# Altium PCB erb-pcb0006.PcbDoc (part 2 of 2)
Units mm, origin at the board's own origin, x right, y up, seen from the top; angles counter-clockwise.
Board outline 100 x 66.5 mm, 4 copper layers (Top Layer, Mid-Layer 1, Mid-Layer 2, Bottom Layer), stack 1.564 mm thick; 134 components, 81 nets, 741 pads, 81 vias.
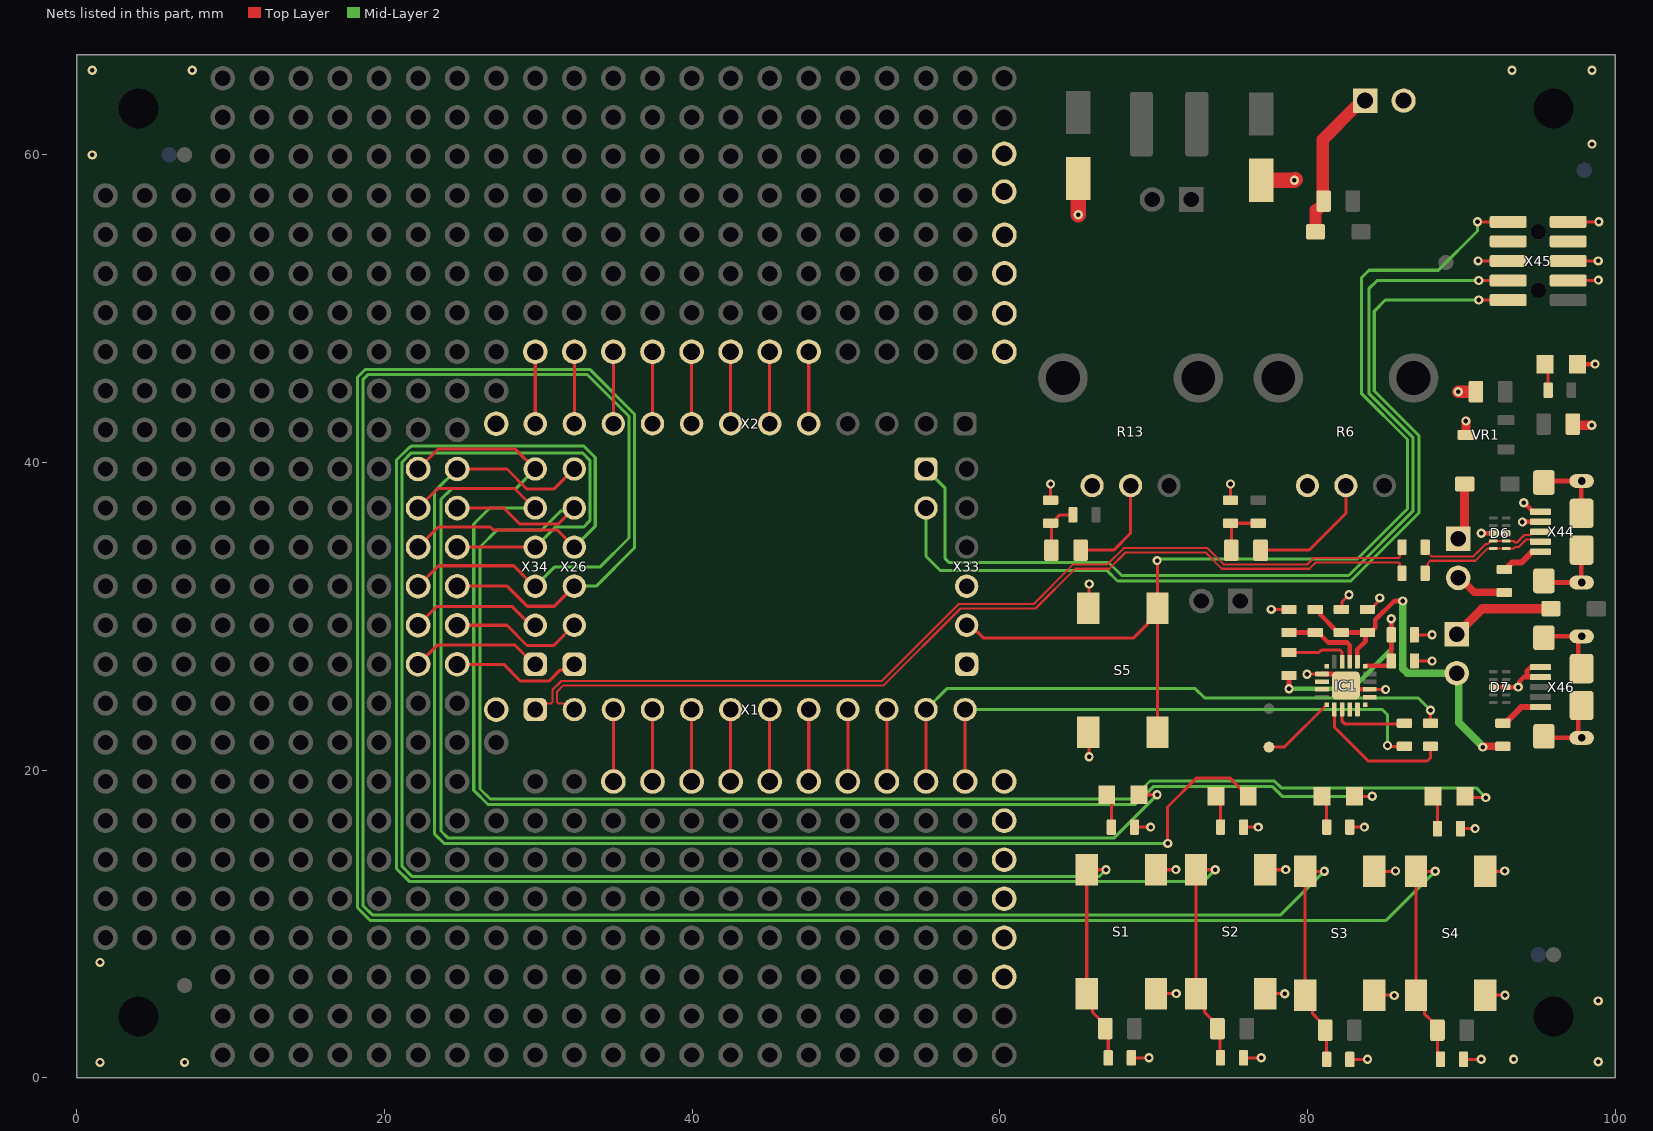
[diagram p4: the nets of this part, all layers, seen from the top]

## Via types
v1: diameter 0.6, hole 0.3, Top Layer to Bottom Layer, 81 vias

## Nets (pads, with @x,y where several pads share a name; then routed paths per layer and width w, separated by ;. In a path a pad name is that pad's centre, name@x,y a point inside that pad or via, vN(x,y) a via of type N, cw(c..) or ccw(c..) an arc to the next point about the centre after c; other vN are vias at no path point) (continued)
GND: C1.2 C2.2 C3.2 C4.2 C5.2 C6.2 C7.2 C8.2 C9.2 C10.2 C11.1 C12.1 C13.1 C14.1 D5.K D6.3 D6.8 D7.3 D7.8 IC1.3 IC1.12 IC1.21 R3.1 R4.1 R6.1 R7.1 R9.1 R13.1 R16.2 S1.3 S1.4 S2.3 S2.4 S3.3 S3.4 S4.3 S4.4 S5.3 S5.4 VR1.3 X33.1 X33.3 X44.4 X44.5 X44.6@95.375,32.3 X44.6@95.375,38.7 X44.6@97.825,32.2 X44.6@97.825,34.3 X44.6@97.825,36.7 X44.6@97.825,38.8 X45.3 X45.5 X45.9 X46.4 X46.5 X46.6@95.375,22.2 X46.6@95.375,28.6 X46.6@97.825,22.1 X46.6@97.825,24.2 X46.6@97.825,26.6 X46.6@97.825,28.7 X47.2 X52.1 X53.1 X54.1 X55.1 X56.1 X57.1 X58.1 X59.1 X60.1 X61.1 X62.1 X63.1 X64.1 X65.1 | length 76.1
  Top Layer w0.2: C7.2@63.3,37.55 v1(63.3,38.6) ; S5.4@65.8,22.1 65.8,20.874 v1(65.803,20.872) ; S5.3@65.8,30.9 65.8,32.092 v1(65.81,32.102) ; C1.2@68.55,1.3 v1(69.7,1.3) ; R3.1@68.95,16.3 v1(69.8,16.3) ; S1.3@70.15,5.475 71.471,5.475 v1(71.472,5.474) ; S1.4@70.15,13.525 71.435,13.525 v1(71.448,13.538) ; C3.2@75,37.55 v1(75,38.6) ; C2.2@75.85,1.3 v1(77,1.3) ; R4.1@76.05,16.3 v1(76.8,16.3) ; S2.3@77.25,5.475 78.509,5.475 v1(78.517,5.466) ; S2.4@77.25,13.525 78.576,13.525 v1(78.587,13.536) ; v1(77.65,30.45) R16.2@78.8,30.45 ; v1@80.021,26.238 80.025,26.243 IC1.12@80.943,26.243 ; C14.1@82.2,30.45 82.233,30.483 82.233,30.933 v1(82.7,31.4) ; C4.2@82.75,1.2 v1(83.9,1.2) ; R7.1@82.95,16.3 v1(83.7,16.3) ; C13.1@83.9,30.45 84.1,30.45 84.3,30.65 84.3,30.66 84.478,30.838 84.546,30.906 84.546,30.938 84.7,31.092 v1(84.7,31.2) ; IC1.3@84.16,25.24 v1(85.078,25.24) ; S3.3@84.35,5.375 85.615,5.375 v1(85.635,5.354) ; S3.4@84.35,13.425 85.704,13.425 v1(85.723,13.444) ; C11.1@86.95,27.1 v1(88.1,27.1) ; C12.1@86.95,28.8 v1(88.1,28.8) ; R9.1@89.95,16.2 v1(90.9,16.2) ; C8.2@90.15,1.2 v1(91.3,1.2) ; S4.3@91.55,5.375 92.828,5.375 v1(92.841,5.362) ; S4.4@91.55,13.425 92.807,13.425 v1(92.826,13.444) ; X45.3@96.95,51.835 98.89,51.835 v1(98.913,51.858) ; X45.5@96.95,53.105 v1(98.905,53.105) ; X45.9@96.95,55.645 v1(98.945,55.645)
  Top Layer w0.3: IC1.12@80.95,26.25 81.316,26.25 81.317,26.251 81.708,26.251 82.409,25.55 IC1.21@82.55,25.55 ; IC1.21@82.5,25.5 82.749,25.251 83.749,25.251 IC1.3@84.05,25.25 ; v1(91.3,35.4) D6.3@92.915,35.4 ; D7.3@92.07,25.4 D7.3@92.085,25.4 D7.8@92.915,25.4 v1(93.7,25.4) 93.757,25.457 93.757,25.745 94.071,26.059 94.441,26.059 ; v1(93.975,36.133) 93.992,36.15 X44.4@95.125,36.15 ; v1(94.056,37.385) 94.083,37.385 94.6,36.868 94.6,36.85 94.65,36.8 X44.5@95.125,36.8 ; 94.45,26.059 94.441,26.059 ; X46.6@95.15,22.2 95.25,22.1 97.6,22.1 X46.6@97.6,24.2 ; X46.4@95.15,26.05 94.45,26.05 94.441,26.059 ; X46.5@95.15,26.7 94.5,26.7 94.274,26.474 94.274,26.226 94.441,26.059 ; X46.6@95.15,28.6 95.25,28.7 97.6,28.7 X46.6@97.6,26.6 ; X44.6@95.35,32.3 95.45,32.2 97.8,32.2 X44.6@97.8,34.3 ; X44.6@95.35,38.7 95.45,38.8 97.8,38.8 X44.6@97.8,36.7 ; D5.K@97.55,46.4 v1(98.7,46.4)
  Top Layer w0.6: VR1.3@90.3,41.8 v1(90.3,42.7) ; C5.2@97.325,42.425 v1(98.475,42.425)
  Top Layer w0.8: v1(89.8,44.6) C6.2@90.63,44.6
  Top Layer w1: v1(65.1,56.1) C10.2@65.1,58.45 ; C9.2@77,58.35 v1(79.15,58.35) v1@79.2,58.4
  other v1: 1.5,1 7,1 98.91,1.05 93.4,1.2 98.9,5 1.5,7.5 79.971,26.238 1,60 98.5,60.7 1,65.5 7.5,65.5 93.3,65.5 98.5,65.5
GPIO1: D1.A X34.6 X40.1 | length 86.3
  Top Layer w0.2: X40.1@22.18,39.58 23.472,40.872 28.508,40.872 X34.6@29.8,39.58 ; D1.A@69.05,18.4 v1(70.225,18.4)
  Mid-Layer 2 w0.2: X34.6@29.8,39.58 28.52,38.3 24.365,38.3 23.67,37.605 23.67,16.047 24.137,15.58 67.405,15.58 v1(70.225,18.4)
GPIO2: D2.A X26.6 X32.1 | length 89.5
  Top Layer w0.2: X32.1@24.72,39.58 27.957,39.58 29.267,38.27 30.996,38.27 X26.6@32.323,39.597 ; v1(70.913,15.236) 70.9,15.249 70.9,17.6 72.8,19.5 74.946,19.5 75.646,18.8 75.876,18.8 D2.A@75.976,18.7
  Mid-Layer 2 w0.2: X32.1@24.72,39.58 23.235,38.095 23.235,15.87 23.875,15.23 70.907,15.23 v1(70.913,15.236)
GPIO3: D3.A X34.5 X39.1 | length 91.1
  Top Layer w0.2: X39.1@22.18,37.04 23.456,38.316 28.445,38.316 29.721,37.04 X34.5@29.8,37.04 ; D3.A@83.05,18.3 v1@84.2,18.3
  Mid-Layer 2 w0.2: X34.5@29.8,37.04 26.84,37.04 25.8,36 25.8,18.695 26.725,17.77 68.817,17.77 69.997,18.95 77.703,18.95 78.353,18.3 v1(84.205,18.3)
GPIO4: D4.A X26.5 X31.1 | length 99.1
  Top Layer w0.2: X31.1@24.72,37.04 27.752,37.04 28.792,36 31.3,36 X26.5@32.34,37.04 ; D4.A@90.25,18.3 90.304,18.304 90.469,18.304 90.587,18.187 90.619,18.219 v1(91.596,18.219)
  Mid-Layer 2 w0.2: X26.5@32.34,37.04 32.14,36.84 31.44,36.84 30.2,35.6 27.3,35.6 26.21,34.51 26.21,18.78 26.87,18.12 68.584,18.12 69.764,19.3 77.848,19.3 78.298,18.85 83.977,18.85 90.966,18.85 v1@91.416,18.399
GPIO5: C1.1 R1.1 S1.1 S1.2 X34.4 X38.1 | length 112.5
  Top Layer w0.2: X38.1@24.72,34.5 X34.4@29.8,34.5 ; v1(66.9,13.525) S1.2@65.65,13.525 S1.1@65.65,5.475 66.026,5.099 66.026,4.267 66.505,3.788 66.526,3.788 66.9,3.415 66.9,3.2 67.05,3.05 C1.1@67.05,1.3
  Mid-Layer 2 w0.2: X34.4@29.8,34.5 31.1,35.8 32.933,35.8 33.35,36.217 33.35,40.15 32.87,40.63 21.745,40.63 21.13,40.015 21.13,13.745 21.775,13.1 66.475,13.1 v1(66.9,13.525)
GPIO6: C2.1 R2.1 S2.1 S2.2 X26.4 X30.1 | length 125.6
  Top Layer w0.2: X30.1@22.18,34.5 23.483,35.803 26.883,35.803 27.076,35.611 31.229,35.611 X26.4@32.34,34.5 ; v1(74,13.525) S2.2@72.75,13.525 S2.1@72.75,5.475 73.311,4.914 73.311,4.267 R2.1@74.15,3.429 ; R2.1@74.15,3.2 74.318,3.032 74.318,1.332 C2.1@74.35,1.3
  Mid-Layer 2 w0.2: X26.4@32.34,34.5 33.7,35.86 33.7,40.325 32.955,41.07 21.745,41.07 21.655,40.98 21.6,40.98 20.78,40.16 20.78,13.6 21.63,12.75 73.225,12.75 v1(74,13.525)
GPIO7: C4.1 R8.1 S3.1 S3.2 X34.3 X37.1 | length 154.7
  Top Layer w0.2: X37.1@22.18,31.96 23.507,33.287 28.394,33.287 X34.3@29.721,31.96 ; v1(81.1,13.425) S3.2@79.85,13.425 S3.1@79.85,5.375 80.336,4.889 80.336,4.167 80.787,3.716 80.787,3.413 81.25,2.95 C4.1@81.25,1.2
  Mid-Layer 2 w0.2: X34.3@29.8,31.96 31.04,33.2 34,33.2 35.89,35.09 35.89,43.01 33.19,45.71 18.91,45.71 18.59,45.39 18.59,11.205 19.205,10.59 78.265,10.59 v1(81.1,13.425)
GPIO8: C8.1 R14.1 S4.1 S4.2 X26.3 X29.1 | length 162
  Top Layer w0.2: X29.1@24.72,31.96 27.978,31.96 29.281,30.657 31.037,30.657 X26.3@32.34,31.96 ; R14.1@88.076,3.688 87.597,4.167 87.597,4.828 S4.1@87.05,5.375 S4.2@87.05,13.425 v1(88.3,13.425) ; R14.1@88.076,3.688 88.45,3.315 C8.1@88.45,1.2
  Mid-Layer 2 w0.2: X26.3@32.34,31.96 33.76,31.96 36.24,34.44 36.24,43.155 33.335,46.06 19.06,46.06 18.765,46.06 18.24,45.535 18.24,45.24 18.24,11.06 19.06,10.24 85.115,10.24 v1(88.3,13.425)
GPIO9: X34.2 X36.1 | length 8.6
  Top Layer w0.2: X36.1@22.18,29.42 23.41,30.65 28.275,30.65 29.505,29.42 X34.2@29.8,29.42
GPIO10: X26.2 X28.1 | length 8.7
  Top Layer w0.2: X28.1@24.72,29.42 27.957,29.42 29.267,28.11 30.996,28.11 X26.2@32.323,29.437
GPIO11: X34.1 X35.1 | length 8.6
  Top Layer w0.2: X35.1@22.18,26.88 23.45,28.15 28.451,28.15 X34.1@29.721,26.88
GPIO12: X26.1 X27.1 | length 8.5
  Top Layer w0.2: X27.1@24.72,26.88 27.752,26.88 28.832,25.8 30.7,25.8 31.399,26.499 31.959,26.499 X26.1@32.34,26.88
GPIO13: X1.3 X21.1 | length 5.1
  Top Layer w0.2: X21.1@34.88,19.26 X1.3@34.88,24.34
GPIO14: X1.4 X19.1 | length 5.1
  Top Layer w0.2: X19.1@37.42,19.26 X1.4@37.42,24.34
GPIO15: X2.12 X4.1 | length 5.1
  Top Layer w0.2: X2.12@29.8,42.12 X4.1@29.8,47.2
I2C_SCL: X1.5 X17.1 | length 5.1
  Top Layer w0.2: X17.1@39.96,19.26 X1.5@39.96,24.34
I2C_SDA: X1.6 X15.1 | length 5.1
  Top Layer w0.2: X15.1@42.5,19.26 X1.6@42.5,24.34
NC_DBG_CON_2.7: X45.7
NC_DBG_CON_2.8: X45.8
NC_GPIO0_CP2102: IC1.2
NC_GPIO1_CP2102: IC1.1
NC_GPIO2_CP2102: IC1.20
NC_GPIO3_CP2102: IC1.19
NC_nSuspend_CP2102: IC1.11
NC_Suspend_CP2102: IC1.14
NC_Wakeup_CP2102: IC1.13
NetC3_1: C3.1 R5.1 R20.1 | length 3.6
  Top Layer w0.2: R5.1@75.05,34.3 75.05,36 C3.1@75,36.05 R20.1@76.8,36.05
NetC7_1: C7.1 R12.1 R21.1 | length 3.6
  Top Layer w0.2: R12.1@63.35,34.3 63.35,36 C7.1@63.3,36.05 63.5,36.05 63.7,36.25 63.7,36.4 63.9,36.6 R21.1@64.8,36.6
NetD1_K: D1.K R3.2 | length 2.2
  Top Layer w0.2: D1.K@66.95,18.4 67.25,18.1 R3.2@67.25,16.3
NetD2_K: D2.K R4.2 | length 2.1
  Top Layer w0.2: D2.K@74.05,18.3 74.35,18 R4.2@74.35,16.3
NetD3_K: D3.K R7.2 | length 2.1
  Top Layer w0.2: D3.K@80.95,18.3 81.25,18 R7.2@81.25,16.3
NetD4_K: D4.K R9.2 | length 1.8
  Top Layer w0.2: R9.2@88.45,16.2 D4.K@88.45,18.05
NetD5_A: D5.A R10.2 | length 1.8
  Top Layer w0.2: D5.A@95.45,46.4 95.65,46.2 R10.2@95.65,44.7
NetD8_1: D8.1 X43.1 | length 3.6
  Top Layer w0.6: X43.1@89.8,35.04 90.2,35.44 D8.1@90.2,38.5
NetD9_1: D9.1 X66.1 | length 6.4
  Top Layer w0.6: X66.1@89.7,28.84 91.36,30.5 D9.1@95.4,30.5
NetD10_1: D10.1 R24.2 X47.1 | length 9.5
  Top Layer w0.8: 80.518,55.595 80.518,56.4 80.625,56.4 81,56.775 81,61 83.137,63.138 83.363,63.138 X47.1@83.75,63.525
NetL2_1: L2.1 X43.2 | length 3.2
  Top Layer w0.5: X43.2@90.035,32.465 90.035,32.376 90.843,31.568 L2.1@92.768,31.568
NetL2_2: L2.2 X44.1 | length 2.9
  Top Layer w0.3: X44.1@94.55,34.15 95.075,34.15 X44.1@95.125,34.2
  Top Layer w0.4: L2.2@92.768,33.068 92.968,33.068 93.068,33.168 93.068,33.266 93.302,33.5 93.9,33.5 X44.1@94.55,34.15
NetL3_2: L3.2 X46.1 | length 2.5
  Top Layer w0.3: L3.2@92.875,23.075 92.925,23.075 93.05,23.2 L3.2@93.05,23.25
  Top Layer w0.4: L3.2@93.05,23.25 93.9,24.1 X46.1@94.925,24.1
NetR5_2: R5.2 R6.2 | length 8.3
  Top Layer w0.2: R5.2@76.95,34.3 76.958,34.308 80.108,34.308 82.5,36.7 R6.2@82.5,38.5
NetR12_2: R12.2 R13.2 | length 6.8
  Top Layer w0.2: R12.2@65.25,34.3 67.4,34.3 68.5,35.4 R13.2@68.5,38.5
nRESET: S5.1 S5.2 X33.2 X45.10 | length 70
  Top Layer w0.2: X33.2@57.74,29.42 58.097,29.42 58.917,28.6 68.7,28.6 69.625,29.525 69.625,29.6 70.175,30.15 S5.1@70.25,30.15 ; v1(70.225,33.625) 70.25,33.6 S5.1@70.25,30.15 ; S5.2@70.25,22.475 S5.1@70.25,30.15 ; v1(91.055,55.645) X45.10@93.05,55.645
  Mid-Layer 2 w0.2: v1(70.225,33.625) 70.325,33.725 83.235,33.725 86.5,36.99 86.5,41.5 83.5,44.5 83.5,52 84,52.5 88.5,52.5 91.055,55.055 v1(91.055,55.645)
nRST_CP2102: IC1.9 R15.2 | length 4.2
  Top Layer w0.2: R15.2@78.8,27.65 80.75,27.65 80.9,27.8 82.124,27.8 82.241,27.683 IC1.9@82.241,27.059
RTS_CP2102: IC1.16 TP3.1 | length 5.4
  Top Layer w0.2: TP3.1@77.2,21.5 77.269,21.5 77.35,21.581 77.35,21.65 TP3.1@77.515,21.65 ; TP3.1@77.5,21.5 78.5,21.5 IC1.16@81.3,24.3
RXD_CP2102: IC1.17 R18.1 | length 9.1
  Top Layer w0.2: IC1.17@81.76,23.94 81.76,22.784 83.945,20.6 87.8,20.6 88,20.8 R18.1@88,21.55
SPI_CLK: X2.7 X14.1 | length 5.1
  Top Layer w0.2: X2.7@42.5,42.12 X14.1@42.5,47.2
SPI_CS1: X2.8 X12.1 | length 5.1
  Top Layer w0.2: X2.8@39.96,42.12 X12.1@39.96,47.2
SPI_CS2: X2.9 X10.1 | length 5.1
  Top Layer w0.2: X2.9@37.42,42.12 X10.1@37.42,47.2
SPI_CS3: X2.10 X8.1 | length 5.1
  Top Layer w0.2: X2.10@34.88,42.12 X8.1@34.88,47.2
SPI_CS4: X2.11 X6.1 | length 5.1
  Top Layer w0.2: X2.11@32.34,42.12 X6.1@32.34,47.2
SPI_MISO: X2.6 X16.1 | length 5.1
  Top Layer w0.2: X2.6@45.04,42.12 X16.1@45.04,47.2
SPI_MOSI: X2.5 X18.1 | length 5.1
  Top Layer w0.2: X2.5@47.58,42.12 X18.1@47.58,47.2
SWCLK: X25.1 X45.4 | length 63.9
  Top Layer w0.2: v1(91.135,51.835) X45.4@93.05,51.835
  Mid-Layer 2 w0.2: X25.1@55.2,39.58 56.448,38.332 56.448,33.753 56.711,33.49 57.422,33.49 63.795,33.49 63.805,33.5 67.067,33.5 67.917,32.65 82.677,32.65 86.85,36.823 86.85,41.645 83.992,44.503 83.992,51.3 84.527,51.835 v1(91.135,51.835)
SWDIO: X25.2 X45.2 | length 61
  Top Layer w0.2: v1(91.135,50.565) X45.2@93.05,50.565
  Mid-Layer 2 w0.2: X25.2@55.2,37.04 55.2,33.916 56.146,32.97 66.985,32.97 67.655,32.3 82.822,32.3 87.25,36.728 87.25,41.74 84.342,44.648 84.342,49.842 85.065,50.565 v1(91.135,50.565)
SWO: X45.6 | length 2.1
  Top Layer w0.2: v1(91.095,53.105) X45.6@93.05,53.105
  Mid-Layer 2 w0.2: v1@91,53 91.095,53.095 v1(91.095,53.105)
TXD_CP2102: IC1.18 R19.1 | length 4.9
  Top Layer w0.2: IC1.18@82.253,23.947 82.253,23.172 82.417,23.008 86.258,23.008 R19.1@86.3,23.05
UART1_CTS: X1.9 X9.1 | length 5.1
  Top Layer w0.2: X9.1@50.12,19.26 X1.9@50.12,24.34
UART1_RTS: X1.10 X7.1 | length 5.1
  Top Layer w0.2: X7.1@52.66,19.26 X1.10@52.66,24.34
UART1_RX: R19.2 X1.12 X3.1 | length 36
  Top Layer w0.2: X3.1@57.74,19.26 X1.12@57.74,23.94 X1.12@57.74,24.34 ; v1(85.2,21.6) 85.25,21.55 R19.2@86.3,21.55
  Mid-Layer 2 w0.2: X1.12@57.74,23.94 84.86,23.94 85.2,23.6 v1@85.2,21.389
UART1_TX: R18.2 X1.11 X5.1 | length 40
  Top Layer w0.2: X5.1@55.2,19.26 X1.11@55.2,23.94 X1.11@55.2,24.34 ; R18.2@88,23.05 v1(88,23.9)
  Mid-Layer 2 w0.2: X1.11@55.2,23.94 56.56,25.3 72.706,25.3 73.316,24.69 87.21,24.69 v1@87.868,24.032 ; X1.11@55.2,24.34 X1.11@55.453,24.593
UART2_RX: X1.8 X11.1 | length 5.1
  Top Layer w0.2: X11.1@47.58,19.26 X1.8@47.58,24.34
UART2_TX: X1.7 X13.1 | length 5.1
  Top Layer w0.2: X13.1@45.04,19.26 X1.7@45.04,24.34
USB_0_D1_N: R22.2 X1.2 | length 61.7
  Top Layer w0.14: X1.2@32.34,24.34 31.297,24.34 31.215,24.422 31.215,25.105 31.62,25.51 52.444,25.51 57.444,30.51 62.32,30.51 64.9,33.09 67.118,33.09 68.173,34.145 73.378,34.145 74.433,33.09 80.119,33.09 80.534,33.505 85.918,33.505 86,33.423 86,32.95 R22.2@86.15,32.8
USB_0_D1_P: R23.2 X1.1 | length 62.2
  Top Layer w0.14: X1.1@29.8,24.34 30.843,24.34 30.925,24.422 30.925,25.225 31.5,25.8 52.324,25.8 57.324,30.8 62.2,30.8 64.78,33.38 66.998,33.38 68.053,34.435 73.498,34.435 74.553,33.38 79.999,33.38 80.414,33.795 85.918,33.795 86,33.877 86,34.35 R23.2@86.15,34.5
USB_0_D_N: D6.1 D6.10 R22.1 X44.2 | length 8.7
  Top Layer w0.14: R22.1@87.65,32.8 87.8,32.95 87.8,33.423 87.987,33.61 90.905,33.61 91.42,34.125 91.712,34.417 91.888,34.417 91.905,34.4 D6.1@92.915,34.4 93.215,34.4 93.395,34.4 93.506,34.511 93.743,34.511 94.145,34.912 94.145,34.914 94.227,34.996 94.529,34.996 94.675,34.85 X44.2@95.125,34.85
USB_0_D_P: D6.2 D6.9 R23.1 X44.3 | length 8.6
  Top Layer w0.14: R23.1@87.65,34.5 87.8,34.35 87.8,34.153 88.053,33.9 90.785,33.9 91.13,34.245 91.592,34.707 91.712,34.707 91.905,34.9 D6.2@92.915,34.9 93.395,34.9 93.494,34.801 93.623,34.801 93.855,35.032 93.855,35.034 94.106,35.286 94.463,35.286 94.545,35.368 94.545,35.37 94.675,35.5 X44.3@95.125,35.5
VBUS: C13.2 C14.2 IC1.7 L3.1 R17.1 X66.2 | length 24.6
  Top Layer w0.3: R17.1@80.5,30.45 80.7,30.45 80.85,30.3 80.85,30.1 81.85,29.1 82,28.95 C14.2@82.2,28.95 83.776,28.95 C13.2@83.9,28.95 ; IC1.7@83.25,27.054 83.25,27.416 83.246,27.42 83.246,27.846 83.776,28.376 83.776,28.826 C13.2@83.9,28.95 ; v1(86.2,31) 85.63,31 84.416,29.785 84.416,29.266 84.1,28.95 C13.2@83.9,28.95
  Top Layer w0.5: v1(91.4,21.5) 91.427,21.5 91.477,21.55 L3.1@92.7,21.55
  Mid-Layer 2 w0.5: v1(86.2,31) 86.2,26.608 86.508,26.3 89.827,26.3 89.827,23.1 v1@91.381,21.546
VBUS_CP2102: IC1.8 R16.1 R17.2 | length 5.4
  Top Layer w0.3: R16.1@78.8,28.95 R17.2@80.5,28.95 80.7,28.95 81.35,28.3 82.58,28.3 82.755,28.124 82.755,27.421 82.75,27.416 IC1.8@82.75,27.055
VDD_CP2102: C11.2 C12.2 IC1.6 R15.1 | length 15.2
  Top Layer w0.3: v1(78.8,25.3) R15.1@78.8,26.15 ; IC1.6@83.8,26.8 85.3,26.8 85.45,26.95 C11.2@85.45,27.1 C12.2@85.45,28.8 v1(85.45,29.85) v1@85.4,29.9
  Mid-Layer 2 w0.3: v1(78.8,25.3) 82.9,25.3 85.45,27.85 v1(85.45,29.85)
pads on no net: D6.4 D6.5 D6.6 D6.7 D7.4 D7.5 D7.6 D7.7 IC1.10 NPN1.0 NPN2.0 NPN3.0 NPN4.0 NPN5.0 NPN6.0 NPN7.0 NPN8.0 R6.NC1 R6.NC2 R13.NC1 R13.NC2 X44.6@97.825,32.2 X44.6@97.825,38.8 X45. X46.6@97.825,22.1 X46.6@97.825,28.7

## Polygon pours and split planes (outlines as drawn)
GND on Bottom Layer "GND_L04_P003" (solid, remove dead copper, pour order 3): 0,66.5 100,66.5 100,0 0,0
GND on Mid-Layer 1 "NONET_L01_P-001" (solid, pour order 4): 0,0 0,66.5 100,66.5 100,0
3V3 on Mid-Layer 2 "NONET_L01_P-001" (solid, remove dead copper, pour order 6): 0,0 0,66.5 100,66.5 100,0

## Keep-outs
Top Layer:
  circle w0.254: c4,63 r2.261
  circle w0.254: c4,4 r2.261
  circle w0.254: c96,4 r2.261
  circle w0.254: c96,63 r2.261
Bottom Layer:
  circle w0.254: c96,63 r2.261
  circle w0.254: c96,4 r2.261
  circle w0.254: c4,4 r2.261
  circle w0.254: c4,63 r2.261

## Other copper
Top Layer:
  text ".Layer_Name" at 139.35,65.05 h1.2
  text ".Layer_Name" at 104.914,65.02 h1.2
Mid-Layer 1:
  text ".Layer_Name" at 139.35,65.05 h1.2
  text ".Layer_Name" at 104.91,65.014 h1.2
Mid-Layer 2:
  text ".Layer_Name" at 139.35,65.05 h1.2
  text ".Layer_Name" at 104.91,65.014 h1.2
Bottom Layer:
  text ".Layer_Name" at 139.35,65.05 h1.2
  text ".Layer_Name" at 104.914,65.02 h1.2

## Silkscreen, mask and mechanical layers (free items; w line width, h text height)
Top Overlay:
  circle w0.15: c60.28,62.44 r1.1
  circle w0.15: c60.28,64.98 r1.1
  circle w0.15: c60.28,1.48 r1.1
  circle w0.15: c60.28,4.02 r1.1
  circle w0.15: c24.72,39.58 r1.1
  circle w0.15: c24.72,37.04 r1.1
  circle w0.15: c24.72,34.5 r1.1
  circle w0.15: c24.72,31.96 r1.1
  circle w0.15: c24.72,29.42 r1.1
  circle w0.15: c24.72,26.88 r1.1
  circle w0.15: c32.34,47.2 r1.1
  circle w0.15: c29.8,47.2 r1.1
  circle w0.15: c34.88,47.2 r1.1
  circle w0.15: c37.42,47.2 r1.1
  circle w0.15: c39.96,47.2 r1.1
  circle w0.15: c42.5,47.2 r1.1
  circle w0.15: c45.04,47.2 r1.1
  circle w0.15: c47.58,47.2 r1.1
  circle w0.15: c50.12,47.2 r1.1
  circle w0.15: c52.66,47.2 r1.1
  circle w0.15: c55.2,47.2 r1.1
  circle w0.15: c57.74,47.2 r1.1
  circle w0.15: c47.58,19.26 r1.1
  circle w0.15: c50.12,19.26 r1.1
  circle w0.15: c52.66,19.26 r1.1
  circle w0.15: c55.2,19.26 r1.1
  circle w0.15: c57.74,19.26 r1.1
  circle w0.15: c34.88,19.26 r1.1
  circle w0.15: c37.42,19.26 r1.1
  circle w0.15: c39.96,19.26 r1.1
  circle w0.15: c42.5,19.26 r1.1
  circle w0.15: c45.04,19.26 r1.1
  circle w0.15: c22.18,26.88 r1.1
  circle w0.15: c22.18,29.42 r1.1
  circle w0.15: c22.18,31.96 r1.1
  circle w0.15: c22.18,34.5 r1.1
  circle w0.15: c22.18,37.04 r1.1
  circle w0.15: c22.18,39.58 r1.1
  lines w0.254: 59,5.2 61.6,5.2 61.6,20.8 59,20.8 59,5.2 ; 59,45.7 61.6,45.7 61.6,61.3 59,61.3 59,45.7
  text "3V3A" at 61.818,64.641 h0.8
  text ".Layer_Name" at 139.35,63.05 h1.2
  text ".Layer_Name" at 104.85,63.025 h1.2
  text "3V3" at 62.519,61.477 h0.8 r90
  text "PWR 5V" at 90.425,60.513 h1.5 r90
  text "Variant:" at 156.9,60.2 h1.2
  text "5V" at 81.832,58.576 h1.5
  text "GND" at 85.372,58.558 h1.5
  text "PGM" at 91.226,56.767 h1.5
  text "3V3A" at 69.709,54.675 h0.8
  text "Analog1" at 63.661,52.482 h1.5
  text "Analog0" at 77.57,52.482 h1.5
  text "GND" at 62.85,52.334 h0.8 r90
  text "Git:" at 88.45,47.65 h1
  text ".VersionControl_ProjFolderRevNumberShort" at 91.775,47.575 h1
  text "GP15" at 28.4,45.01 h0.8
  text "SCS3" at 33.414,45.01 h0.8
  text "SCS1" at 38.627,45.01 h0.8
  text "MISO" at 43.64,45.01 h0.8
  text "AI3" at 49.12,45.01 h0.8
  text "AI1" at 54.334,45.01 h0.8
  text "SCS4" at 30.874,43.74 h0.8
  text "SCS2" at 35.954,43.74 h0.8
  text "SCLK" at 41.034,43.74 h0.8
  text "MOSI" at 46.247,43.74 h0.8
  text "AI2" at 51.66,43.74 h0.8
  text "AI0" at 56.74,43.74 h0.8
  text "USB" at 94.91,39.917 h1.5
  text "GP1" at 27.029,39.155 h0.8 r90
  text "GP2" at 28.299,39.022 h0.8 r90
  text "CLK" at 60.05,38.814 h0.8 r90
  text "Boot" at 61.55,38.667 h0.8 r90
  text "5V" at 87.416,38.131 h1.5
  text "USB" at 86.423,36.695 h1.5
  text "IO" at 60.05,36.4 h0.8 r90
  text "GP3" at 27.029,36.228 h0.8 r90
  text "GP4" at 28.299,36.228 h0.8 r90
  text "3V3" at 61.625,35.929 h0.8 r90
  text "3V3A" at 59.167,34.05 h0.8
  text "GP5" at 27.029,33.434 h0.8 r90
  text "GP6" at 28.299,33.434 h0.8 r90
  text "RST" at 66.768,32.109 h1.5
  text "GND" at 59.167,31.55 h0.8
  text "GP7" at 27.029,30.894 h0.8 r90
  text "GP8" at 28.299,30.894 h0.8 r90
  text "Reset" at 59.167,29.05 h0.8
  text "GP9" at 27.029,27.846 h0.8 r90
  text "GP10" at 28.299,27.766 h0.8 r90
  text "VBUS" at 92.783,26.913 h1.5 r90
  text "GND" at 59.167,26.55 h0.8
  text "Boot" at 76.525,26.092 h0.8 r90
  text "GP11" at 27.029,24.598 h0.8 r90
  text "GP12" at 28.299,24.464 h0.8 r90
  text "USBN" at 30.874,21.79 h0.8
  text "GP14" at 36.02,21.79 h0.8
  text "SDA" at 41.434,21.79 h0.8
  text "RX2" at 46.514,21.79 h0.8
  text "CTS1" at 51.433,21.79 h0.8
  text "RX1" at 56.807,21.79 h0.8
  text "USBP" at 28.68,20.58 h0.8
  text "GP13" at 33.48,20.52 h0.8
  text "SCL" at 38.894,20.52 h0.8
  text "TX2" at 43.974,20.52 h0.8
  text "RTS1" at 48.843,20.52 h0.8
  text "TX1" at 54.267,20.52 h0.8
  text "DBG" at 94.241,20.017 h1.5
  text "LED1" at 66.495,19.475 h1.5
  text "LED4" at 87.554,19.475 h1.5
  text "LED2" at 73.507,19.375 h1.5
  text "LED3" at 80.402,19.391 h1.5
  text "B1" at 67.402,13.85 h1.5
  text "B2" at 74.414,13.85 h1.5
  text "B3" at 81.509,13.767 h1.5
  text "B4" at 88.712,13.75 h1.5
  text "GND" at 62.635,11.594 h0.8 r90
  text "2025/04/10" at 96.625,10.59 h0.8 r90
  text "erb-pcb0006" at 95.308,9.566 h0.8 r90
  text "G-Base-1 Rev 0.3" at 94.025,5.825 h0.8 r90
  text "3V3" at 61.734,3.59 h0.8
  text "3V3" at 61.734,1.05 h0.8
Bottom Overlay:
  text ".Layer_Name" at 139.35,63.05 h1.2
  text ".Layer_Name" at 104.85,63.025 h1.2
  text "Variant:" at 156.9,60.2 h1.2
  text "DEV::BLOCK" at 88.8,55.222 h2
  text "Agile Hardware Design" at 88.8,52.576 h2
  text "info@dev-block.com" at 88.906,49.9 h2
  text "Design Files" at 89.8,21.576 h2
  text "https://github.com/DEV-BLOCK-IO/" at 89.8,19.576 h2
  text "Documentation:" at 89.8,10.22 h2
  text "www.dev-block.com/docs" at 89.8,8.222 h2
Top Paste:
  text ".Layer_Name" at 139.35,61.05 h1.2
  text ".Layer_Name" at 104.85,61.025 h1.2
Bottom Paste:
  text ".Layer_Name" at 139.35,61.05 h1.2
  text ".Layer_Name" at 104.85,61.025 h1.2
Top Solder:
  text ".Layer_Name" at 139.35,59.05 h1.2
  text ".Layer_Name" at 104.85,59.025 h1.2
Bottom Solder:
  text ".Layer_Name" at 139.35,59.1 h1.2
  text ".Layer_Name" at 104.85,59.075 h1.2
Mechanical 1:
  lines w0.05: 62.075,45.515 62.075,45.515 ; 62.075,45.515 62.075,45.515
  lines w0.254: 99.96,0 0,0 0,66.5 8,66.5 99.96,66.5 99.96,2.2
  text ".Layer_Name" at 139.35,57.35 h1.2
  text ".Layer_Name" at 104.85,57.325 h1.2
Mechanical 2:
  lines w0.05: 62.075,21.42 62.075,21.42 ; 62.075,21.42 62.075,21.42 ; 62.075,21.42 62.075,21.42
  lines w0.1: 62.075,45.515 62.075,45.515
  text ".Layer_Name" at 139.35,55.834 h1.2
  text ".Layer_Name" at 104.85,55.809 h1.2
  text "all dimensions in mm" at 35.463,-7.16 h1.52
Top Assembly:
  text ".Layer_Name" at 104.85,54.325 h1.2
  text ".Layer_Name" at 139.35,54.35 h1.2
Drill Drawing:
  circle w0.254: c106.717,-0.751 r0.536
  lines w0.254: 106.181,2.199 107.254,2.199 106.717,1.127 106.181,2.199 ; 106.181,3.54 107.254,3.54 107.254,4.613 106.181,4.613 106.181,3.54 ; 106.181,5.954 106.181,6.222 106.449,6.49 106.181,6.759 106.181,7.027 106.449,7.027 106.717,6.759 106.986,7.027 107.254,7.027 107.254,6.759 106.986,6.49 107.254,6.222 107.254,5.954 106.986,5.954 106.717,6.222 106.449,5.954 106.181,5.954 ; 106.181,8.368 107.254,8.368 107.254,9.441 106.181,9.441 106.181,8.368 ; 106.181,10.781 106.717,11.05 107.254,10.781 106.986,11.318 107.254,11.854 106.717,11.586 106.181,11.854 106.449,11.318 106.181,10.781 ; 106.181,13.732 106.717,13.195 107.254,13.732 106.717,14.268 106.181,13.732 ; 106.181,15.877 106.449,15.877 106.449,15.609 106.986,15.609 106.986,15.877 107.254,15.877 107.254,16.414 106.986,16.414 106.986,16.682 106.449,16.682 106.449,16.414 106.181,16.414 106.181,15.877 ; 106.396,8.582 107.039,8.582 107.039,9.226 106.396,9.226 106.396,8.582
  lines w0.381: 104.836,27.976 111.981,27.976 127.975,27.976 142.778,27.976 154.007,27.976 163.875,27.976 ; 104.836,30.019 111.981,30.019 127.975,30.019 142.778,30.019 154.007,30.019 163.875,30.019 ; 104.836,32.062 111.981,32.062 127.975,32.062 142.778,32.062 154.007,32.062 163.875,32.062 ; 104.836,34.104 111.981,34.104 127.975,34.104 142.778,34.104 154.007,34.104 163.875,34.104 ; 104.836,36.147 111.981,36.147 127.975,36.147 142.778,36.147 154.007,36.147 163.875,36.147 ; 104.836,38.19 111.981,38.19 127.975,38.19 142.778,38.19 154.007,38.19 163.875,38.19 ; 104.836,40.232 111.981,40.232 127.975,40.232 142.778,40.232 154.007,40.232 163.875,40.232 ; 104.836,42.275 111.981,42.275 127.975,42.275 142.778,42.275 154.007,42.275 163.875,42.275 ; 104.836,44.318 111.981,44.318 127.975,44.318 142.778,44.318 154.007,44.318 163.875,44.318 ; 104.836,46.36 111.981,46.36 127.975,46.36 142.778,46.36 154.007,46.36 163.875,46.36 ; 104.836,48.403 163.875,48.403 ; 105.19,-2.011 268.135,-2.011 ; 105.19,17.299 268.135,17.299 ; 111.981,50.446 111.981,25.934 ; 114.352,-4.425 114.352,19.712 ; 124.191,-4.425 124.191,19.712 ; 127.975,50.446 127.975,25.934 ; 142.778,50.446 142.778,25.934 ; 142.877,-4.425 142.877,19.712 ; 151.315,-4.425 151.315,19.712 ; 154.007,50.446 154.007,25.934 ; 163.421,-4.425 163.421,19.712 ; 187.737,-4.425 187.737,19.712 ; 197.527,-4.425 197.527,19.712 ; 209.826,-4.425 209.826,19.712 ; 227.547,-4.425 227.547,19.712 ; 245.267,-4.425 245.267,19.712 ; 111.981,25.934 104.836,25.934 104.836,50.446 163.875,50.446 163.875,25.934 154.007,25.934 ; 111.981,25.934 127.975,25.934 ; 127.975,25.934 142.778,25.934 ; 142.778,25.934 154.007,25.934 ; 105.19,-4.425 268.135,-4.425 268.135,19.712 105.19,19.712 105.19,-4.425
  text "PCB File:" at 156.9,64.2 h1.2
  text ".Pcb_File_Name_No_Path" at 170.4,64.2 h1.2
  text "Print Date:" at 156.9,62.2 h1.2
  text ".Print_Date" at 170.4,62.2 h1.2
  text "Variant:" at 156.9,60.2 h1.2
  text ".VariantName" at 170.4,60.2 h1.2
  text "Layer" at 106.111,48.914 h1.02
  text "Name" at 113.257,48.914 h1.02
  text "Material" at 129.25,48.914 h1.02
  text "Thickness" at 144.053,48.914 h1.02
  text "Constant" at 155.282,48.914 h1.02
  text "Top Overlay" at 113.257,46.871 h1.02
  text "Top Solder" at 113.257,44.828 h1.02
  text "Solder Resist" at 129.25,44.828 h1.02
  text "0,010mm" at 144.053,44.828 h1.02
  text "3.5" at 155.282,44.828 h1.02
  text "1" at 106.111,42.786 h1.02
  text "Top Layer" at 113.257,42.786 h1.02
  text "0,035mm" at 144.053,42.786 h1.02
  text "Dielectric 1" at 113.257,40.743 h1.02
  text "FR-4" at 129.25,40.743 h1.02
  text "0,099mm" at 144.053,40.743 h1.02
  text "4.8" at 155.282,40.743 h1.02
  text "2" at 106.111,38.7 h1.02
  text "Mid-Layer 1" at 113.257,38.7 h1.02
  text "0,015mm" at 144.053,38.7 h1.02
  text "Dielectric3" at 113.257,36.658 h1.02
  text "FR-4" at 129.25,36.658 h1.02
  text "1,265mm" at 144.053,36.658 h1.02
  text "4.8" at 155.282,36.658 h1.02
  text "3" at 106.111,34.615 h1.02
  text "Mid-Layer 2" at 113.257,34.615 h1.02
  text "0,015mm" at 144.053,34.615 h1.02
  text "Dielectric2" at 113.257,32.572 h1.02
  text "FR-4" at 129.25,32.572 h1.02
  text "0,099mm" at 144.053,32.572 h1.02
  text "4.8" at 155.282,32.572 h1.02
  text "4" at 106.111,30.53 h1.02
  text "Bottom Layer" at 113.257,30.53 h1.02
  text "0,035mm" at 144.053,30.53 h1.02
  text "Bottom Solder" at 113.257,28.487 h1.02
  text "Solder Resist" at 129.25,28.487 h1.02
  text "0,010mm" at 144.053,28.487 h1.02
  text "3.5" at 155.282,28.487 h1.02
  text "Bottom Overlay" at 113.257,26.444 h1.02
  text "Symbol" at 106.638,18.023 h1.16
  text "Count" at 115.076,18.023 h1.16
  text "Hole Size" at 124.915,18.023 h1.16
  text "Plated" at 143.601,18.023 h1.16
  text "Hole Type" at 152.039,18.023 h1.16
  text "Drill Layer Pair" at 164.145,18.023 h1.16
  text "Via/Pad" at 188.461,18.023 h1.16
  text "Pad Shape" at 198.251,18.023 h1.16
  text "Template" at 210.55,18.023 h1.16
  text "Hole Length" at 228.271,18.023 h1.16
  text "Routed Path Length" at 245.992,18.023 h1.16
  text "2" at 115.076,15.609 h0.97
  text "1.050mm (41.34mil)" at 124.915,15.609 h0.97
  text "PTH" at 143.601,15.609 h0.97
  text "Round" at 152.039,15.609 h0.97
  text "Top Layer - Bottom Layer" at 164.145,15.609 h0.97
  text "Pad" at 188.461,15.609 h0.97
  text "(Mixed)" at 198.251,15.609 h0.97
  text "(Mixed)" at 210.55,15.609 h0.97
  text "-" at 228.271,15.609 h0.97
  text "-" at 245.992,15.609 h0.97
  text "4" at 115.076,13.195 h0.97
  text "0.500mm (19.69mil)" at 124.915,13.195 h0.97
  text "PTH" at 143.601,13.195 h0.97
  text "Slot" at 152.039,13.195 h0.97
  text "Top Layer - Bottom Layer" at 164.145,13.195 h0.97
  text "Pad" at 188.461,13.195 h0.97
  text "Rounded" at 198.251,13.195 h0.97
  text "r160_90h50_120r45" at 210.55,13.195 h0.97
  text "1.200mm (47.24mil)" at 228.271,13.195 h0.97
  text "0.700mm (27.56mil)" at 245.992,13.195 h0.97
  text "4" at 115.076,10.781 h0.97
  text "2.200mm (86.61mil)" at 124.915,10.781 h0.97
  text "PTH" at 143.601,10.781 h0.97
  text "Round" at 152.039,10.781 h0.97
  text "Top Layer - Bottom Layer" at 164.145,10.781 h0.97
  text "Pad" at 188.461,10.781 h0.97
  text "Rounded" at 198.251,10.781 h0.97
  text "c322h220" at 210.55,10.781 h0.97
  text "-" at 228.271,10.781 h0.97
  text "-" at 245.992,10.781 h0.97
  text "4" at 115.076,8.368 h0.97
  text "2.600mm (102.36mil)" at 124.915,8.368 h0.97
  text "NPTH" at 143.601,8.368 h0.97
  text "Round" at 152.039,8.368 h0.97
  text "Top Layer - Bottom Layer" at 164.145,8.368 h0.97
  text "Pad" at 188.461,8.368 h0.97
  text "Rounded" at 198.251,8.368 h0.97
  text "c200hn260" at 210.55,8.368 h0.97
  text "-" at 228.271,8.368 h0.97
  text "-" at 245.992,8.368 h0.97
  text "46" at 115.076,5.954 h0.97
  text "1.020mm (40.16mil)" at 124.915,5.954 h0.97
  text "PTH" at 143.601,5.954 h0.97
  text "Round" at 152.039,5.954 h0.97
  text "Top Layer - Bottom Layer" at 164.145,5.954 h0.97
  text "Pad" at 188.461,5.954 h0.97
  text "(Mixed)" at 198.251,5.954 h0.97
  text "(Mixed)" at 210.55,5.954 h0.97
  text "-" at 228.271,5.954 h0.97
  text "-" at 245.992,5.954 h0.97
  text "52" at 115.076,3.54 h0.97
  text "1.100mm (43.31mil)" at 124.915,3.54 h0.97
  text "PTH" at 143.601,3.54 h0.97
  text "Round" at 152.039,3.54 h0.97
  text "Top Layer - Bottom Layer" at 164.145,3.54 h0.97
  text "Pad" at 188.461,3.54 h0.97
  text "Rounded" at 198.251,3.54 h0.97
  text "c160h110" at 210.55,3.54 h0.97
  text "-" at 228.271,3.54 h0.97
  text "-" at 245.992,3.54 h0.97
  text "81" at 115.076,1.127 h0.97
  text "0.300mm (11.81mil)" at 124.915,1.127 h0.97
  text "PTH" at 143.601,1.127 h0.97
  text "Round" at 152.039,1.127 h0.97
  text "Top Layer - Bottom Layer" at 164.145,1.127 h0.97
  text "Via" at 188.461,1.127 h0.97
  text "Rounded" at 198.251,1.127 h0.97
  text "v60h30" at 210.55,1.127 h0.97
  text "-" at 228.271,1.127 h0.97
  text "-" at 245.992,1.127 h0.97
  text "431" at 115.076,-1.287 h0.97
  text "1.000mm (39.37mil)" at 124.915,-1.287 h0.97
  text "PTH" at 143.601,-1.287 h0.97
  text "Round" at 152.039,-1.287 h0.97
  text "Top Layer - Bottom Layer" at 164.145,-1.287 h0.97
  text "Pad" at 188.461,-1.287 h0.97
  text "(Mixed)" at 198.251,-1.287 h0.97
  text "(Mixed)" at 210.55,-1.287 h0.97
  text "-" at 228.271,-1.287 h0.97
  text "-" at 245.992,-1.287 h0.97
  text "624 Total" at 115.076,-3.701 h0.97
  text "Slot definitions :" at 106.638,-6.22 h0.97
  text "Routed Path Length" at 123.516,-6.22 h0.97
  text "= Calculated from tool start centre position to tool end centre position." at 141.521,-6.22 h0.97
  text "Hole Length" at 123.516,-8.015 h0.97
  text "= Routed Path Length + Tool Size = Slot length as defined in the PCB layout" at 134.925,-8.015 h0.97

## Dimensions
0,0 to 0,66.5 on Mechanical 2
0,0 to 100,-1 on Mechanical 2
